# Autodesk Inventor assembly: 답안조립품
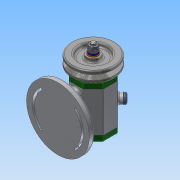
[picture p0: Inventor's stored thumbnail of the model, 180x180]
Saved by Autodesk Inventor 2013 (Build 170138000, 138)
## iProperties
Created: 2017-06
Part Number: 답안조립품
Document SubType Name: Assembly
Designer: Administrator
Author: Administrator
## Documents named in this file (14)
- C:\Users\Administrator\Desktop\470608V1021\답안조립품.iam
- C:\Users\Administrator\Desktop\470608V1021\본체1.ipt
- C:\Users\Administrator\Desktop\470608V1021\V벨트풀리.ipt
- C:\Users\Administrator\Desktop\470608V1021\고무캡.ipt
- C:\Users\Administrator\Desktop\470608V1021\너트 M 8.ipt
- C:\Users\Administrator\Desktop\470608V1021\뒤커버.ipt
- C:\Users\Administrator\Desktop\470608V1021\베어링 15 x 32 x 9.ipt
- C:\Users\Administrator\Desktop\470608V1021\볼트 M4 x 12.ipt
- C:\Users\Administrator\Desktop\470608V1021\스프링와셔 8.ipt
- C:\Users\Administrator\Desktop\470608V1021\앞커버.ipt
- C:\Users\Administrator\Desktop\470608V1021\오일 실 15 25 7.ipt
- C:\Users\Administrator\Desktop\470608V1021\와셔 8x17.ipt
- C:\Users\Administrator\Desktop\470608V1021\축.ipt
- C:\Users\Administrator\Desktop\470608V1021\키 3 x 3 x 12.ipt
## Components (2 placed, 2 different names)
1. V벨트풀리:1
2. 고무캡:1
